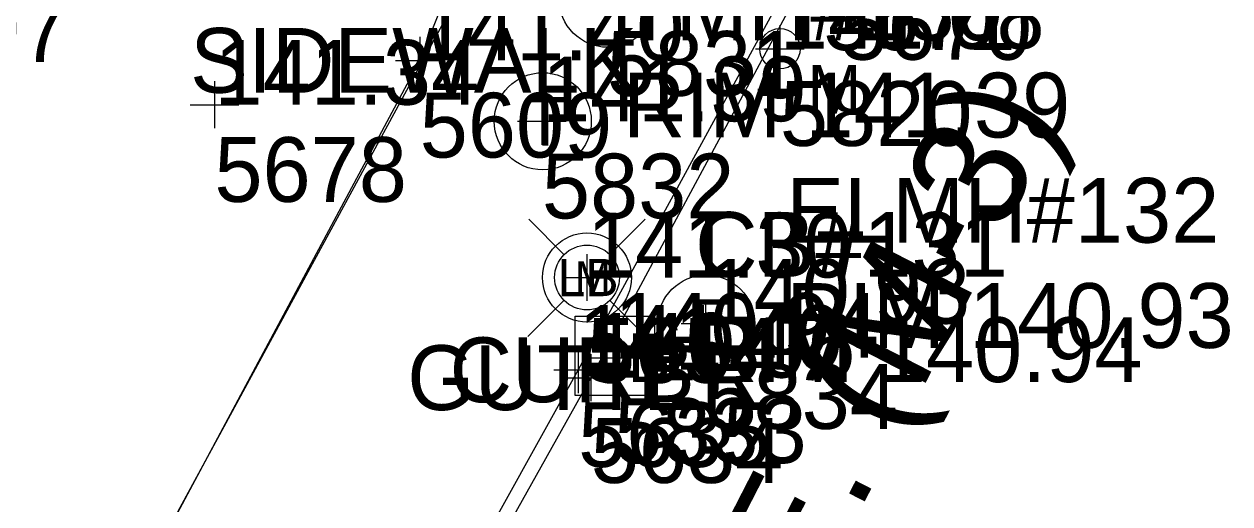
# Model space of a CAD drawing. Extents: x 13482495 to 13483389, y 311646 to 312209.
# Drawn here: x 13483245.5 to 13483305.2, y 312019.7 to 312043.4 of the extents above; entities that cross this region are included whole.
import ezdxf

# ---------------------------------------------------------------- set-up
doc = ezdxf.new("R2010")
doc.units = 0
for name, color, linetype in [('Level 14', 7, 'Continuous'), ('V-ANNO-TEXT', 7, 'Continuous'), ('v-comm-iden', 7, 'Continuous'), ('V-COMM-JBOX', 7, 'Continuous'), ('V-ELEC-JBOX', 7, 'Continuous'), ('V-ELEC-OVHD-IDEN', 7, 'Continuous'), ('V-PROP-RWAY', 7, 'Continuous'), ('V-PVMT-BACK', 7, 'Continuous'), ('V-PVMT-ROAD', 7, 'Continuous'), ('V-PVMT-SPOT', 7, 'Continuous'), ('V-SITE-FEAT', 7, 'Continuous'), ('V-SITE-SPOT', 7, 'Continuous'), ('V-SITE-WALK', 7, 'Continuous'), ('V-STRM-MHOL', 7, 'Continuous'), ('V-STRM-MHOL-IDEN', 7, 'Continuous'), ('V-SURV-PNTS', 7, 'Continuous'), ('V-TOPO-DRAN-SPOT', 7, 'Continuous'), ('V-TOPO-LINE-IDEN', 7, 'Continuous'), ('V-TOPO-SPOT', 7, 'Continuous'), ('V-UTIL-OVHD', 7, 'Continuous'), ('V-UTIL-SPOT', 7, 'Continuous')]:
    doc.layers.add(name, color=color, linetype=linetype)

msp = doc.modelspace()

# ---------------------------------------------------------------- linework, layer by layer
at = {"layer": 'Level 14'}
msp.add_circle((13483273.366, 312030.908), 2.2, dxfattribs=at)
at = {"layer": 'V-COMM-JBOX'}
for centre in [(13483274.383, 312044.683), (13483271.179, 312038.627)]:
    msp.add_circle(centre, 2.4, dxfattribs=at)
at = {"layer": 'V-ELEC-JBOX'}
msp.add_circle((13483279.262, 312028.629), 2.4, dxfattribs=at)
at = {"layer": 'V-PROP-RWAY'}
msp.add_line((13483192.658, 311908.098), (13483276.388, 312062.114), dxfattribs=at)
at = {"layer": 'V-PVMT-BACK'}
msp.add_lwpolyline([(13483265.367, 312065.469), (13483266.904, 312067.158), (13483268.711, 312068.553), (13483270.734, 312069.612), (13483272.91, 312070.302), (13483275.173, 312070.603), (13483277.454, 312070.505), (13483279.683, 312070.011), (13483279.844, 312069.959), (13483281.692, 312068.707), (13483283.459, 312067.111), (13483284.934, 312065.242), (13483286.077, 312063.153), (13483286.685, 312061.511), (13483287.334, 312059.111), (13483287.694, 312057.052), (13483287.657, 312054.963), (13483287.224, 312052.919), (13483286.819, 312051.835), (13483272.932, 312026.347), (13483261.444, 312005.675), (13483260.181, 312004.285), (13483258.653, 312003.194), (13483257.491, 312002.645)], dxfattribs=at)
at = {"layer": 'V-PVMT-ROAD'}
msp.add_lwpolyline([(13483264.812, 312066.093), (13483266.499, 312067.784), (13483268.445, 312069.171), (13483270.595, 312070.215), (13483272.888, 312070.886), (13483275.261, 312071.165), (13483277.648, 312071.046), (13483279.981, 312070.531), (13483279.987, 312070.529), (13483281.988, 312069.166), (13483283.778, 312067.617), (13483285.281, 312065.789), (13483286.456, 312063.735), (13483287.215, 312061.702), (13483287.934, 312059.343), (13483288.263, 312057.108), (13483288.193, 312054.85), (13483287.727, 312052.639), (13483287.382, 312051.654), (13483273.552, 312025.959), (13483262.051, 312005.407), (13483253.537, 311989.252), (13483242.277, 311968.929), (13483232.654, 311951.179)], dxfattribs=at)
at = {"layer": 'V-PVMT-SPOT'}
for p, q in [((13483265.094, 312042.797), (13483265.094, 312040.477)), ((13483263.894, 312041.637), (13483266.294, 312041.637)), ((13483272.932, 312027.507), (13483272.932, 312025.187)), ((13483273.552, 312027.119), (13483273.552, 312024.799)), ((13483271.732, 312026.347), (13483274.132, 312026.347)), ((13483272.352, 312025.959), (13483274.752, 312025.959))]:
    msp.add_line(p, q, dxfattribs=at)
at = {"layer": 'V-SITE-FEAT'}
msp.add_circle((13483282.905, 312042.211), 1, dxfattribs=at)
at = {"layer": 'V-SITE-SPOT'}
for p, q in [((13483282.905, 312043.371), (13483282.905, 312041.051)), ((13483281.705, 312042.211), (13483284.105, 312042.211))]:
    msp.add_line(p, q, dxfattribs=at)
at = {"layer": 'V-SITE-WALK'}
msp.add_lwpolyline([(13483219.99, 311958.205), (13483240.127, 311995.062), (13483265.094, 312041.637), (13483269.475, 312052.418), (13483267.261, 312057.854), (13483264.689, 312064.334), (13483265.367, 312065.469)], dxfattribs=at)
at = {"layer": 'V-STRM-MHOL'}
for p, q in [((13483272.786, 312028.997), (13483276.706, 312028.997)), ((13483272.786, 312025.077), (13483272.786, 312028.997)), ((13483276.706, 312028.997), (13483276.706, 312025.077)), ((13483276.706, 312025.077), (13483272.786, 312025.077))]:
    msp.add_line(p, q, dxfattribs=at)
msp.add_lwpolyline([(13483272.786, 312028.997), (13483276.706, 312028.997), (13483276.706, 312025.077), (13483272.786, 312025.077)], close=True, dxfattribs=at)
at = {"layer": 'V-TOPO-DRAN-SPOT'}
for p, q in [((13483274.712, 312028.102), (13483274.712, 312025.782)), ((13483273.512, 312026.942), (13483275.912, 312026.942))]:
    msp.add_line(p, q, dxfattribs=at)
at = {"layer": 'V-TOPO-SPOT'}
for p, q in [((13483254.945, 312040.605), (13483254.945, 312038.285)), ((13483253.745, 312039.445), (13483256.145, 312039.445))]:
    msp.add_line(p, q, dxfattribs=at)
at = {"layer": 'V-UTIL-OVHD'}
for p, q in [((13483272.246, 312032.028), (13483270.486, 312033.788)), ((13483274.486, 312032.028), (13483276.246, 312033.788)), ((13483270.446, 312027.988), (13483272.246, 312029.788)), ((13483276.166, 312028.108), (13483274.486, 312029.788))]:
    msp.add_line(p, q, dxfattribs=at)
msp.add_circle((13483273.366, 312030.908), 1.6, dxfattribs=at)
at = {"layer": 'V-UTIL-SPOT'}
for p, q in [((13483271.139, 312039.787), (13483271.139, 312037.467)), ((13483269.939, 312038.627), (13483272.339, 312038.627)), ((13483273.366, 312032.068), (13483273.366, 312029.748)), ((13483273.366, 312032.068), (13483273.366, 312029.748)), ((13483272.166, 312030.908), (13483274.566, 312030.908)), ((13483272.166, 312030.908), (13483274.566, 312030.908)), ((13483279.222, 312029.789), (13483279.222, 312027.469)), ((13483278.022, 312028.629), (13483280.422, 312028.629))]:
    msp.add_line(p, q, dxfattribs=at)

# ---------------------------------------------------------------- texts
at = {"layer": 'V-ANNO-TEXT'}
for s, rotation, p in [('ADELAIDE ST. (50 FT WD)', 27.03125, (13483190.121, 312032.547)), ('GRATIOT AVE. (M-3)', 62.80661, (13483263.78, 311974.454))]:
    msp.add_text(s, height=5.6, rotation=rotation, dxfattribs=at).set_placement(p)
at = {"layer": 'v-comm-iden'}
for s, p in [('TMH#130', (13483275.139, 312042.627)), ('RIM 141.39', (13483275.139, 312037.827))]:
    msp.add_text(s, height=3.2, dxfattribs=at).set_placement(p)
at = {"layer": 'V-COMM-JBOX'}
msp.add_text('T', height=2.4, rotation=360, dxfattribs=at).set_placement((13483270.335, 312037.427))
at = {"layer": 'V-ELEC-JBOX'}
msp.add_text('E', height=2.4, rotation=360, dxfattribs=at).set_placement((13483278.505, 312027.429))
at = {"layer": 'V-ELEC-OVHD-IDEN'}
for s, p in [('ELMH#132', (13483283.222, 312032.629)), ('RIM 140.93', (13483283.222, 312027.429))]:
    msp.add_text(s, height=3.2, dxfattribs=at).set_placement(p)
at = {"layer": 'V-PVMT-SPOT'}
for s, p in [('140.97', (13483234.648, 312041.555)), ('141.40', (13483265.094, 312041.637)), ('141.40', (13483272.932, 312026.347)), ('140.96', (13483273.552, 312025.959))]:
    msp.add_text(s, height=3.2, dxfattribs=at).set_placement(p)
at = {"layer": 'V-SITE-FEAT'}
msp.add_text('M', height=2.4, rotation=360, dxfattribs=at).set_placement((13483284.265, 312039.011))
at = {"layer": 'V-SITE-SPOT'}
msp.add_text('141.08', height=3.2, dxfattribs=at).set_placement((13483282.905, 312042.211))
at = {"layer": 'V-STRM-MHOL'}
msp.add_text('CB', height=2.4, rotation=360, dxfattribs=at).set_placement((13483273.064, 312025.742))
at = {"layer": 'V-STRM-MHOL-IDEN'}
for s, p in [('CB#131', (13483278.712, 312030.942)), ('RIM 140.94', (13483278.712, 312025.742))]:
    msp.add_text(s, height=3.2, dxfattribs=at).set_placement(p)
at = {"layer": 'V-SURV-PNTS'}
for s, p in [('5671', (13483285.042, 312042.141)), ('5670', (13483285.851, 312041.669)), ('5831', (13483274.343, 312039.883)), ('5820', (13483282.905, 312037.411)), ('5609', (13483265.094, 312036.837)), ('5678', (13483254.945, 312034.645)), ('5832', (13483271.139, 312033.827)), ('5654', (13483273.366, 312025.708)), ('5654', (13483273.366, 312025.708)), ('5834', (13483279.222, 312023.429)), ('5635', (13483272.932, 312021.547)), ('5833', (13483274.712, 312021.742)), ('5634', (13483273.552, 312020.759))]:
    msp.add_text(s, height=3.2, dxfattribs=at).set_placement(p)
at = {"layer": 'V-TOPO-DRAN-SPOT'}
msp.add_text('140.94', height=3.2, dxfattribs=at).set_placement((13483274.712, 312026.942))
at = {"layer": 'V-TOPO-LINE-IDEN'}
for s, p in [('SIDEWALK', (13483253.744, 312040.037)), ('GUTTER', (13483264.481, 312024.359)), (' CURB', (13483265.385, 312024.747))]:
    msp.add_text(s, height=3.2, dxfattribs=at).set_placement(p)
at = {"layer": 'V-TOPO-SPOT'}
msp.add_text('141.34', height=3.2, dxfattribs=at).set_placement((13483254.945, 312039.445))
at = {"layer": 'V-UTIL-OVHD'}
for s, height, p in [('LB', 1.8432, (13483271.914, 312029.986)), ('M', 1.6, (13483272.767, 312030.108))]:
    msp.add_text(s, height=height, rotation=360, dxfattribs=at).set_placement(p)
at = {"layer": 'V-UTIL-SPOT'}
for s, p in [('141.39', (13483271.139, 312038.627)), ('141.30', (13483273.366, 312030.908)), ('141.30', (13483273.366, 312030.908)), ('140.93', (13483279.222, 312028.629))]:
    msp.add_text(s, height=3.2, dxfattribs=at).set_placement(p)

doc.saveas('drawing.dxf')
